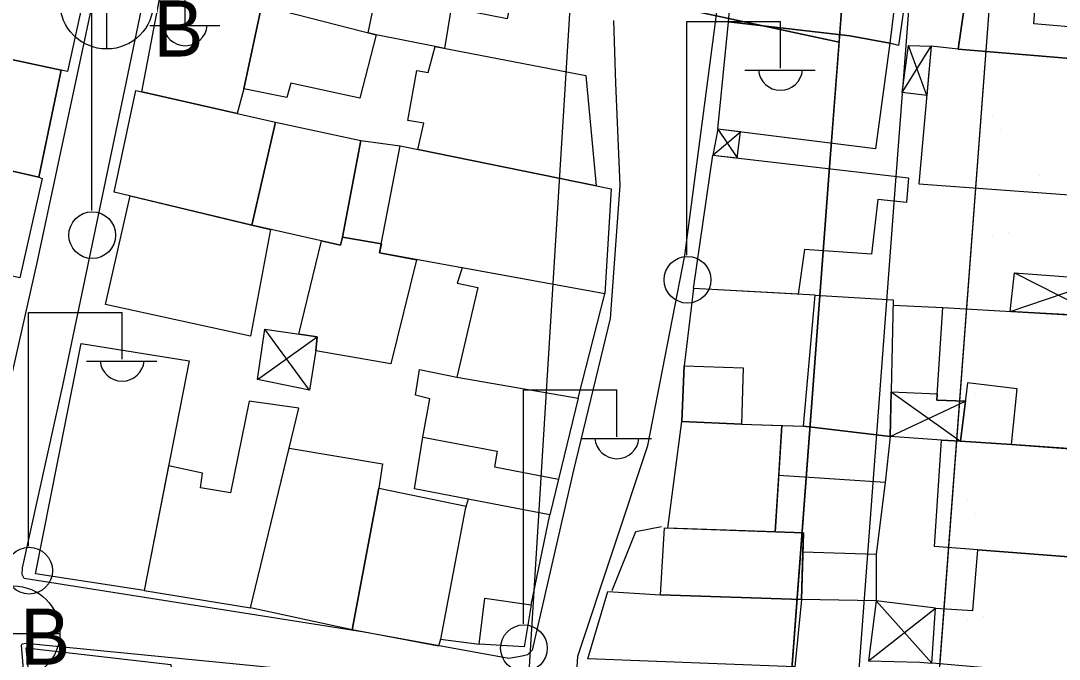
# Model space of a CAD drawing. Extents: x 417997 to 421451, y 4451742 to 4455216.
# Drawn here: x 419872.8 to 419950.6, y 4452801.1 to 4452848.9 of the extents above; entities that cross this region are included whole.
import ezdxf

# ---------------------------------------------------------------- set-up
doc = ezdxf.new("R2010")
doc.units = 0
for name, color, linetype in [('ADA', 7, 'Continuous'), ('ADAKENARI', 7, 'Continuous'), ('B_Mesken', 7, 'Continuous'), ('B_Sundurma', 7, 'Continuous'), ('B_Teras', 7, 'Continuous'), ('Default', 7, 'Continuous'), ('KALDIRIM', 7, 'Continuous'), ('PL_REKRASYON', 7, 'Continuous'), ('PL_SAY_DINI_TESIS', 7, 'Continuous'), ('PL_TİCK', 7, 'Continuous'), ('S_Elektrik_Diregi', 7, 'Continuous'), ('S_Rogar_Kapagi', 7, 'Continuous'), ('S_Rogar_Kapagi_Buski', 7, 'Continuous'), ('Sinir_Duvar_tek_tarafa_ait', 7, 'Continuous'), ('SN_KENTSEL_DONUSUM', 7, 'Continuous'), ('TR_PARKALANI', 7, 'Continuous'), ('TR_TİCK', 7, 'Continuous'), ('Yol_Sose', 7, 'Continuous')]:
    doc.layers.add(name, color=color, linetype=linetype)

# ---------------------------------------------------------------- blocks, each defined once
blk = doc.blocks.new('POINT_DISPLAY')
at = {"layer": 'Default'}
blk.add_line((0, 0), (0, 0), dxfattribs=at)

msp = doc.modelspace()

# ---------------------------------------------------------------- linework, layer by layer
at = {"layer": 'ADA'}
msp.add_line((419891.593, 4452856.399), (419934.109, 4452847.264), dxfattribs=at)
msp.add_line((419891.593, 4452856.399), (419934.109, 4452847.264), dxfattribs=at)
at = {"layer": 'ADAKENARI'}
for p, q in [((419951.73, 4452934.958), (419936.731, 4452735.371)), ((419951.73, 4452934.958), (419936.731, 4452735.371)), ((419934.794, 4452856.377), (419933.356, 4452837.245)), ((419934.794, 4452856.377), (419933.356, 4452837.245)), ((419933.356, 4452837.245), (419924.806, 4452723.471)), ((419933.356, 4452837.245), (419924.806, 4452723.471))]:
    msp.add_line(p, q, dxfattribs=at)
at = {"layer": 'B_Mesken'}
for points in [[(419938.906, 4452855.359), (419942.178, 4452855.045), (419941.801, 4452852.537), (419939.392, 4452852.78), (419938.567, 4452846.993), (419937.919, 4452847.18), (419934.908, 4452847.723), (419925.824, 4452848.778), (419926.575, 4452856.956)], [(419866.427, 4452855.5), (419878.074, 4452853.055), (419876.334, 4452845.047), (419875.853, 4452845.156), (419867.491, 4452846.956), (419868.207, 4452851.034), (419865.892, 4452851.584)], [(419910.176, 4452853.87), (419909.248, 4452848.991), (419905.066, 4452849.821), (419904.562, 4452846.785), (419903.86, 4452846.919), (419899.435, 4452847.81), (419898.838, 4452847.962), (419900.481, 4452855.731), (419905.207, 4452854.911)], [(419943.583, 4452850.518), (419943.941, 4452854.499), (419957.52, 4452853.221), (419956.808, 4452845.142), (419952.617, 4452845.925), (419943.039, 4452846.723)], [(419881.897, 4452843.544), (419883.39, 4452851.416), (419890.87, 4452849.956), (419889.54, 4452843.768), (419889.031, 4452841.921)], [(419889.54, 4452843.768), (419890.87, 4452849.956), (419891.456, 4452849.842), (419899.435, 4452847.81), (419898.213, 4452843.071), (419893.052, 4452844.193), (419892.756, 4452843.101)], [(419860.042, 4452844.286), (419858.955, 4452840.852), (419864.853, 4452839.268), (419874.182, 4452837.157), (419875.853, 4452845.156), (419861.43, 4452848.261)], [(419937.919, 4452847.18), (419936.847, 4452839.277), (419925.037, 4452840.747), (419925.824, 4452848.778), (419934.908, 4452847.723)], [(419902.576, 4452839.217), (419903.024, 4452841.187), (419901.825, 4452841.381), (419902.496, 4452845.124), (419903.341, 4452844.991), (419903.86, 4452846.919), (419915.152, 4452844.769), (419915.923, 4452836.495)], [(419943.039, 4452846.723), (419941.01, 4452846.953), (419940.073, 4452836.644), (419955.468, 4452835.521), (419956.808, 4452845.142), (419952.617, 4452845.925)], [(419891.913, 4452841.265), (419890.132, 4452833.557), (419879.834, 4452836.025), (419881.454, 4452843.644)], [(419898.31, 4452839.903), (419896.927, 4452832.662), (419896.787, 4452832.05), (419890.132, 4452833.557), (419891.913, 4452841.265)], [(419859.973, 4452836.532), (419860.858, 4452840.341), (419864.853, 4452839.268), (419874.182, 4452837.157), (419874.431, 4452837.047), (419872.751, 4452829.614), (419863.264, 4452831.644), (419860.396, 4452832.257), (419858.612, 4452832.798), (419859.544, 4452836.632)], [(419899.836, 4452832.142), (419896.927, 4452832.662), (419898.31, 4452839.903), (419901.254, 4452839.487), (419917.038, 4452836.267), (419916.569, 4452828.421), (419899.705, 4452831.469)], [(419923.219, 4452828.803), (419924.647, 4452838.799), (419939.321, 4452837.105), (419939.151, 4452835.246), (419937.009, 4452835.463), (419936.547, 4452831.375), (419931.511, 4452831.731), (419931.049, 4452828.38)], [(419891.545, 4452833.237), (419890.035, 4452825.241), (419879.183, 4452827.604), (419881.017, 4452835.741), (419890.132, 4452833.557)], [(419893.657, 4452825.389), (419895.351, 4452832.376), (419896.787, 4452832.05), (419896.927, 4452832.662), (419899.836, 4452832.142), (419899.705, 4452831.469), (419902.476, 4452830.968), (419900.543, 4452823.181), (419894.934, 4452824.15), (419895.018, 4452825.18)], [(419905.896, 4452830.35), (419905.508, 4452829.217), (419907.055, 4452828.888), (419905.49, 4452822.177), (419914.58, 4452820.602), (419916.569, 4452828.421)], [(419926.812, 4452818.65), (419931.44, 4452818.512), (419932.312, 4452828.312), (419923.219, 4452828.803), (419922.512, 4452823.026), (419922.329, 4452818.858)], [(419932.312, 4452828.312), (419938.158, 4452827.965), (419937.941, 4452817.73), (419931.44, 4452818.512)], [(419943.567, 4452820.384), (419941.425, 4452820.448), (419941.872, 4452827.382), (419954.287, 4452826.671), (419953.385, 4452816.669), (419947.021, 4452817.14), (419943.216, 4452817.373)], [(419873.931, 4452807.452), (419877.353, 4452824.689), (419885.43, 4452823.383), (419882.062, 4452806.187)], [(419914.58, 4452820.602), (419913.104, 4452814.533), (419912.455, 4452811.867), (419906.326, 4452813.025), (419902.32, 4452813.803), (419902.935, 4452817.675), (419903.455, 4452820.551), (419902.4, 4452820.818), (419902.693, 4452822.749), (419905.49, 4452822.177)], [(419882.062, 4452806.187), (419890.045, 4452804.895), (419893.661, 4452819.856), (419889.923, 4452820.368), (419888.531, 4452813.499), (419886.28, 4452813.877), (419886.447, 4452814.974), (419883.89, 4452815.521)], [(419921.295, 4452810.873), (419922.329, 4452818.858), (419926.812, 4452818.65), (419929.823, 4452818.56), (419929.329, 4452810.593)], [(419937.941, 4452817.73), (419937.572, 4452814.289), (419936.9, 4452808.912), (419936.886, 4452805.418), (419931.289, 4452805.523), (419931.401, 4452809.093), (419931.445, 4452810.52), (419929.329, 4452810.593), (419929.59, 4452814.797), (419929.823, 4452818.56), (419931.44, 4452818.512)], [(419953.087, 4452816.691), (419952.293, 4452808.644), (419941.255, 4452809.502), (419941.775, 4452817.463), (419943.216, 4452817.373), (419947.021, 4452817.14)], [(419892.933, 4452816.842), (419899.913, 4452815.691), (419899.639, 4452813.864), (419897.655, 4452803.242), (419890.045, 4452804.895)], [(419899.639, 4452813.864), (419906.18, 4452812.504), (419906.118, 4452812.284), (419904.258, 4452802.56), (419904.111, 4452802.024), (419897.655, 4452803.242)], [(419904.258, 4452802.56), (419907.152, 4452802.182), (419907.589, 4452805.623), (419911.043, 4452805.124), (419912.455, 4452811.867), (419906.326, 4452813.025), (419906.118, 4452812.284)], [(419921.044, 4452810.881), (419931.445, 4452810.52), (419931.289, 4452805.523), (419920.738, 4452805.862)], [(419952.293, 4452808.644), (419951.531, 4452799.803), (419951.146, 4452799.875), (419941.05, 4452800.744), (419941.332, 4452804.88), (419944.135, 4452804.709), (419944.505, 4452809.249)], [(419920.738, 4452805.862), (419931.289, 4452805.523), (419930.795, 4452800.472), (419915.307, 4452801.085), (419916.799, 4452806.115), (419920.738, 4452805.862)], [(419884.057, 4452800.653), (419885.057, 4452789.962), (419874.594, 4452789.045), (419873.248, 4452801.907)]]:
    msp.add_lwpolyline(points, close=True, dxfattribs=at)
at = {"layer": 'B_Sundurma'}
for p, q in [((419938.834, 4452843.486), (419941.01, 4452846.953)), ((419940.675, 4452843.261), (419939.299, 4452847.002)), ((419924.647, 4452838.799), (419926.724, 4452840.537)), ((419925.037, 4452840.747), (419926.471, 4452838.589)), ((419946.917, 4452827.093), (419953.938, 4452829.476)), ((419947.24, 4452829.976), (419953.683, 4452826.706)), ((419894.462, 4452821.203), (419891.112, 4452825.756)), ((419890.565, 4452821.997), (419895.018, 4452825.18)), ((419938.012, 4452821.068), (419943.216, 4452817.373)), ((419937.941, 4452817.73), (419943.567, 4452820.384)), ((419936.886, 4452805.418), (419941.05, 4452800.744)), ((419936.315, 4452800.93), (419941.332, 4452804.88))]:
    msp.add_line(p, q, dxfattribs=at)
for points in [[(419940.675, 4452843.261), (419938.834, 4452843.486), (419939.299, 4452847.002), (419941.01, 4452846.953)], [(419925.037, 4452840.747), (419924.647, 4452838.799), (419926.471, 4452838.589), (419926.724, 4452840.537)], [(419946.917, 4452827.093), (419947.24, 4452829.976), (419953.938, 4452829.476), (419953.683, 4452826.706)], [(419894.939, 4452824.178), (419894.462, 4452821.203), (419890.565, 4452821.997), (419891.112, 4452825.756), (419894.202, 4452825.311), (419895.018, 4452825.18)], [(419941.775, 4452817.463), (419937.941, 4452817.73), (419938.012, 4452821.068), (419941.456, 4452820.929), (419941.425, 4452820.448), (419943.567, 4452820.384), (419943.216, 4452817.373)], [(419936.886, 4452805.418), (419936.315, 4452800.93), (419940.147, 4452800.822), (419941.05, 4452800.744), (419941.332, 4452804.88)]]:
    msp.add_lwpolyline(points, close=True, dxfattribs=at)
at = {"layer": 'B_Teras'}
for points in [[(419925.824, 4452848.778), (419926.575, 4452856.956), (419938.906, 4452855.359), (419937.919, 4452847.18), (419934.908, 4452847.723)], [(419943.583, 4452850.518), (419943.039, 4452846.723), (419952.617, 4452845.925), (419952.763, 4452848.266), (419948.696, 4452848.64), (419948.808, 4452849.99)], [(419860.042, 4452844.286), (419861.43, 4452848.261), (419875.853, 4452845.156), (419874.182, 4452837.157), (419864.853, 4452839.268), (419865.639, 4452843.096)], [(419860.396, 4452832.257), (419858.612, 4452832.798), (419859.544, 4452836.632), (419863.925, 4452835.609), (419864.853, 4452839.268), (419874.182, 4452837.157), (419874.431, 4452837.047), (419872.751, 4452829.614), (419863.264, 4452831.644)], [(419899.705, 4452831.469), (419901.254, 4452839.487), (419917.038, 4452836.267), (419916.569, 4452828.421)], [(419922.512, 4452823.026), (419926.927, 4452822.881), (419926.812, 4452818.65), (419922.329, 4452818.858)], [(419943.727, 4452821.757), (419943.216, 4452817.373), (419947.021, 4452817.14), (419947.443, 4452821.291)], [(419929.823, 4452818.56), (419931.44, 4452818.512), (419937.941, 4452817.73), (419937.572, 4452814.289), (419929.59, 4452814.797)], [(419906.326, 4452813.025), (419902.32, 4452813.803), (419902.935, 4452817.675), (419908.51, 4452816.633), (419908.306, 4452815.464), (419913.104, 4452814.533), (419912.455, 4452811.867)], [(419936.886, 4452805.418), (419931.289, 4452805.523), (419931.401, 4452809.093), (419936.9, 4452808.912)]]:
    msp.add_lwpolyline(points, close=True, dxfattribs=at)
at = {"layer": 'KALDIRIM'}
for p, q in [((419939.78, 4452856.002), (419938.342, 4452836.87)), ((419939.78, 4452856.002), (419938.342, 4452836.87)), ((419938.342, 4452836.87), (419929.403, 4452717.922)), ((419938.342, 4452836.87), (419929.403, 4452717.922))]:
    msp.add_line(p, q, dxfattribs=at)
at = {"layer": 'PL_REKRASYON'}
msp.add_lwpolyline([(419951.73, 4452934.958), (419936.731, 4452735.371), (419935.757, 4452722.409)], dxfattribs=at)
msp.add_lwpolyline([(419951.73, 4452934.958), (419936.731, 4452735.371), (419935.757, 4452722.409)], dxfattribs=at)
at = {"layer": 'PL_SAY_DINI_TESIS'}
msp.add_lwpolyline([(419881.829, 4452858.497), (419891.593, 4452856.399), (419934.109, 4452847.264), (419934.794, 4452856.377), (419938.138, 4452900.871), (419892.986, 4452909.779), (419881.829, 4452858.497)], dxfattribs=at)
msp.add_lwpolyline([(419881.829, 4452858.497), (419891.593, 4452856.399), (419934.109, 4452847.264), (419934.794, 4452856.377), (419938.138, 4452900.871), (419892.986, 4452909.779), (419881.829, 4452858.497)], dxfattribs=at)
at = {"layer": 'PL_TİCK'}
msp.add_lwpolyline([(419818.495, 4452872.106), (419817.924, 4452862.054), (419807.299, 4452703.817), (419809.188, 4452699.395), (419811.509, 4452696.274), (419815.277, 4452693.129), (419818.763, 4452691.403), (419823.409, 4452690.346), (419828.112, 4452690.44), (419837.938, 4452691.844), (419839.646, 4452692.305), (419919.353, 4452713.837), (419924.554, 4452720.127), (419924.806, 4452723.471), (419933.356, 4452837.245), (419934.109, 4452847.264), (419891.593, 4452856.399), (419881.829, 4452858.497), (419872.919, 4452860.412), (419818.495, 4452872.106)], dxfattribs=at)
msp.add_lwpolyline([(419818.495, 4452872.106), (419817.924, 4452862.054), (419807.299, 4452703.817), (419809.188, 4452699.395), (419811.509, 4452696.274), (419815.277, 4452693.129), (419818.763, 4452691.403), (419823.409, 4452690.346), (419828.112, 4452690.44), (419837.938, 4452691.844), (419839.646, 4452692.305), (419919.353, 4452713.837), (419924.554, 4452720.127), (419924.806, 4452723.471), (419933.356, 4452837.245), (419934.109, 4452847.264), (419891.593, 4452856.399), (419881.829, 4452858.497), (419872.919, 4452860.412), (419818.495, 4452872.106)], dxfattribs=at)
at = {"layer": 'S_Elektrik_Diregi'}
for p, q in [((419878.145, 4452834.638), (419878.145, 4452852.138)), ((419885.145, 4452848.638), (419885.145, 4452852.138)), ((419882.485, 4452848.498), (419887.735, 4452848.498)), ((419922.723, 4452831.299), (419922.723, 4452848.799)), ((419922.723, 4452848.799), (419929.723, 4452848.799)), ((419929.723, 4452845.299), (419929.723, 4452848.799)), ((419927.063, 4452845.159), (419932.313, 4452845.159)), ((419873.421, 4452809.518), (419873.421, 4452827.018)), ((419873.421, 4452827.018), (419880.421, 4452827.018)), ((419880.421, 4452823.518), (419880.421, 4452827.018)), ((419877.761, 4452823.378), (419883.011, 4452823.378)), ((419910.473, 4452803.711), (419910.473, 4452821.211)), ((419910.473, 4452821.211), (419917.473, 4452821.211)), ((419917.473, 4452817.711), (419917.473, 4452821.211)), ((419914.813, 4452817.571), (419920.063, 4452817.571))]:
    msp.add_line(p, q, dxfattribs=at)
for centre in [(419878.181, 4452832.802), (419922.759, 4452829.463), (419873.457, 4452807.683), (419910.509, 4452801.875)]:
    msp.add_circle(centre, 1.75, dxfattribs=at)
for centre in [(419885.145, 4452848.65), (419929.724, 4452845.312), (419880.422, 4452823.531), (419917.474, 4452817.724)]:
    msp.add_arc(centre, 1.658, 184.83843, 355.14641, dxfattribs=at)
at = {"layer": 'S_Rogar_Kapagi'}
msp.add_line((419868.751, 4452802.977), (419875.751, 4452802.977), dxfattribs=at)
msp.add_circle((419872.268, 4452803.04), 3.5, dxfattribs=at)
at = {"layer": 'S_Rogar_Kapagi_Buski'}
msp.add_line((419879.263, 4452853.744), (419879.263, 4452846.744), dxfattribs=at)
msp.add_circle((419879.263, 4452850.244), 3.5, dxfattribs=at)
at = {"layer": 'Sinir_Duvar_tek_tarafa_ait'}
for points in [[(419938.149, 4452827.554), (419941.872, 4452827.382)], [(419917.129, 4452806.194), (419918.88, 4452810.612), (419920.825, 4452810.996)], [(419911.043, 4452805.124), (419910.524, 4452801.967), (419907.152, 4452802.182)]]:
    msp.add_lwpolyline(points, dxfattribs=at)
at = {"layer": 'SN_KENTSEL_DONUSUM'}
msp.add_line((419906.016, 4452720.508), (419920.369, 4452953.753), dxfattribs=at)
msp.add_line((419906.016, 4452720.508), (419920.369, 4452953.753), dxfattribs=at)
at = {"layer": 'TR_TİCK'}
msp.add_lwpolyline([(419924.554, 4452720.127), (419924.806, 4452723.471), (419933.356, 4452837.245), (419934.109, 4452847.264), (419891.593, 4452856.399), (419881.829, 4452858.497), (419872.919, 4452860.412), (419818.495, 4452872.106), (419817.924, 4452862.054), (419807.299, 4452703.817), (419809.188, 4452699.395), (419811.509, 4452696.274), (419815.277, 4452693.129), (419818.763, 4452691.403), (419823.409, 4452690.346), (419828.112, 4452690.44), (419837.938, 4452691.844), (419839.646, 4452692.305), (419919.353, 4452713.837), (419924.554, 4452720.127)], dxfattribs=at)
msp.add_lwpolyline([(419924.554, 4452720.127), (419924.806, 4452723.471), (419933.356, 4452837.245), (419934.109, 4452847.264), (419891.593, 4452856.399), (419881.829, 4452858.497), (419872.919, 4452860.412), (419818.495, 4452872.106), (419817.924, 4452862.054), (419807.299, 4452703.817), (419809.188, 4452699.395), (419811.509, 4452696.274), (419815.277, 4452693.129), (419818.763, 4452691.403), (419823.409, 4452690.346), (419828.112, 4452690.44), (419837.938, 4452691.844), (419839.646, 4452692.305), (419919.353, 4452713.837), (419924.554, 4452720.127)], dxfattribs=at)
at = {"layer": 'Yol_Sose'}
for points in [[(419917.215, 4452848.873), (419917.362, 4452844.19), (419917.698, 4452836.514), (419916.974, 4452826.553), (419914.216, 4452815.198), (419911.13, 4452801.734), (419910.774, 4452801.379), (419910.378, 4452801.275), (419909.392, 4452801.11), (419898.545, 4452803.082), (419873.088, 4452807.1), (419872.933, 4452807.39), (419872.962, 4452807.886), (419875.973, 4452821.537), (419880.854, 4452844.783), (419883.912, 4452859.589)], [(419947.103, 4452716.449), (419947.492, 4452697.763), (419946.847, 4452697.634), (419945.759, 4452697.551), (419929.239, 4452700.34), (419922.031, 4452701.736), (419921.783, 4452701.943), (419921.691, 4452702.505), (419919.438, 4452723.017), (419916.589, 4452750.075), (419913.69, 4452775.327), (419913.363, 4452781.854), (419914.539, 4452801.276), (419919.78, 4452817.05), (419922.565, 4452831.29), (419925.936, 4452856.942)], [(419878.479, 4452851.554), (419874.067, 4452830.865), (419868.778, 4452807.445), (419868.572, 4452807.226), (419868.343, 4452807.096), (419867.567, 4452807.078), (419848.005, 4452808.802), (419848.068, 4452804.696), (419868.491, 4452803.964), (419868.688, 4452803.745), (419868.896, 4452803.175), (419870.089, 4452788.726), (419871.952, 4452766.29), (419873.156, 4452754.436), (419873.029, 4452753.787), (419872.806, 4452753.539), (419852.992, 4452750.741)], [(419890.835, 4452695.319), (419884.621, 4452693.964), (419884.386, 4452694.047), (419884.064, 4452694.245), (419882.518, 4452705.787), (419879.725, 4452731.392), (419877.252, 4452755.959), (419874.64, 4452780.828), (419872.881, 4452802.111), (419872.946, 4452802.201), (419873.205, 4452802.256), (419897.848, 4452799.826), (419905.56, 4452798.117), (419906.343, 4452797.419), (419906.705, 4452796.868), (419907.42, 4452786.99), (419910.669, 4452756.951), (419914.518, 4452728.439), (419917.814, 4452701.696), (419917.575, 4452701.216), (419917.219, 4452701.044), (419916.222, 4452700.692), (419910.457, 4452699.481)]]:
    msp.add_lwpolyline(points, dxfattribs=at)

# ---------------------------------------------------------------- block references
at = {"layer": 'TR_PARKALANI', "xscale": 0.1, "yscale": 0.10000000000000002}
for p in [(419949.085, 4452846.276), (419949.085, 4452846.276), (419945.572, 4452841.76), (419945.572, 4452841.76), (419946.212, 4452840.716), (419946.212, 4452840.716), (419949.085, 4452837.25), (419949.085, 4452837.25), (419945.572, 4452832.734), (419945.572, 4452832.734), (419946.822, 4452832.998), (419946.822, 4452832.998), (419944.331, 4452820.972), (419944.331, 4452820.972), (419947.204, 4452817.507), (419947.204, 4452817.507), (419949.83, 4452817.391), (419949.83, 4452817.391), (419943.692, 4452812.99), (419943.692, 4452812.99), (419944.331, 4452811.946), (419944.331, 4452811.946), (419947.204, 4452808.481), (419947.204, 4452808.481), (419943.692, 4452803.965), (419943.692, 4452803.965), (419944.941, 4452804.229), (419944.941, 4452804.229)]:
    msp.add_blockref('POINT_DISPLAY', p, dxfattribs=at)

# ---------------------------------------------------------------- texts
at = {"layer": 'S_Rogar_Kapagi_Buski'}
for p in [(419882.763, 4452846.18), (419872.783, 4452800.641)]:
    msp.add_text('B', height=4.2, dxfattribs=at).set_placement(p)

doc.saveas('drawing.dxf')
